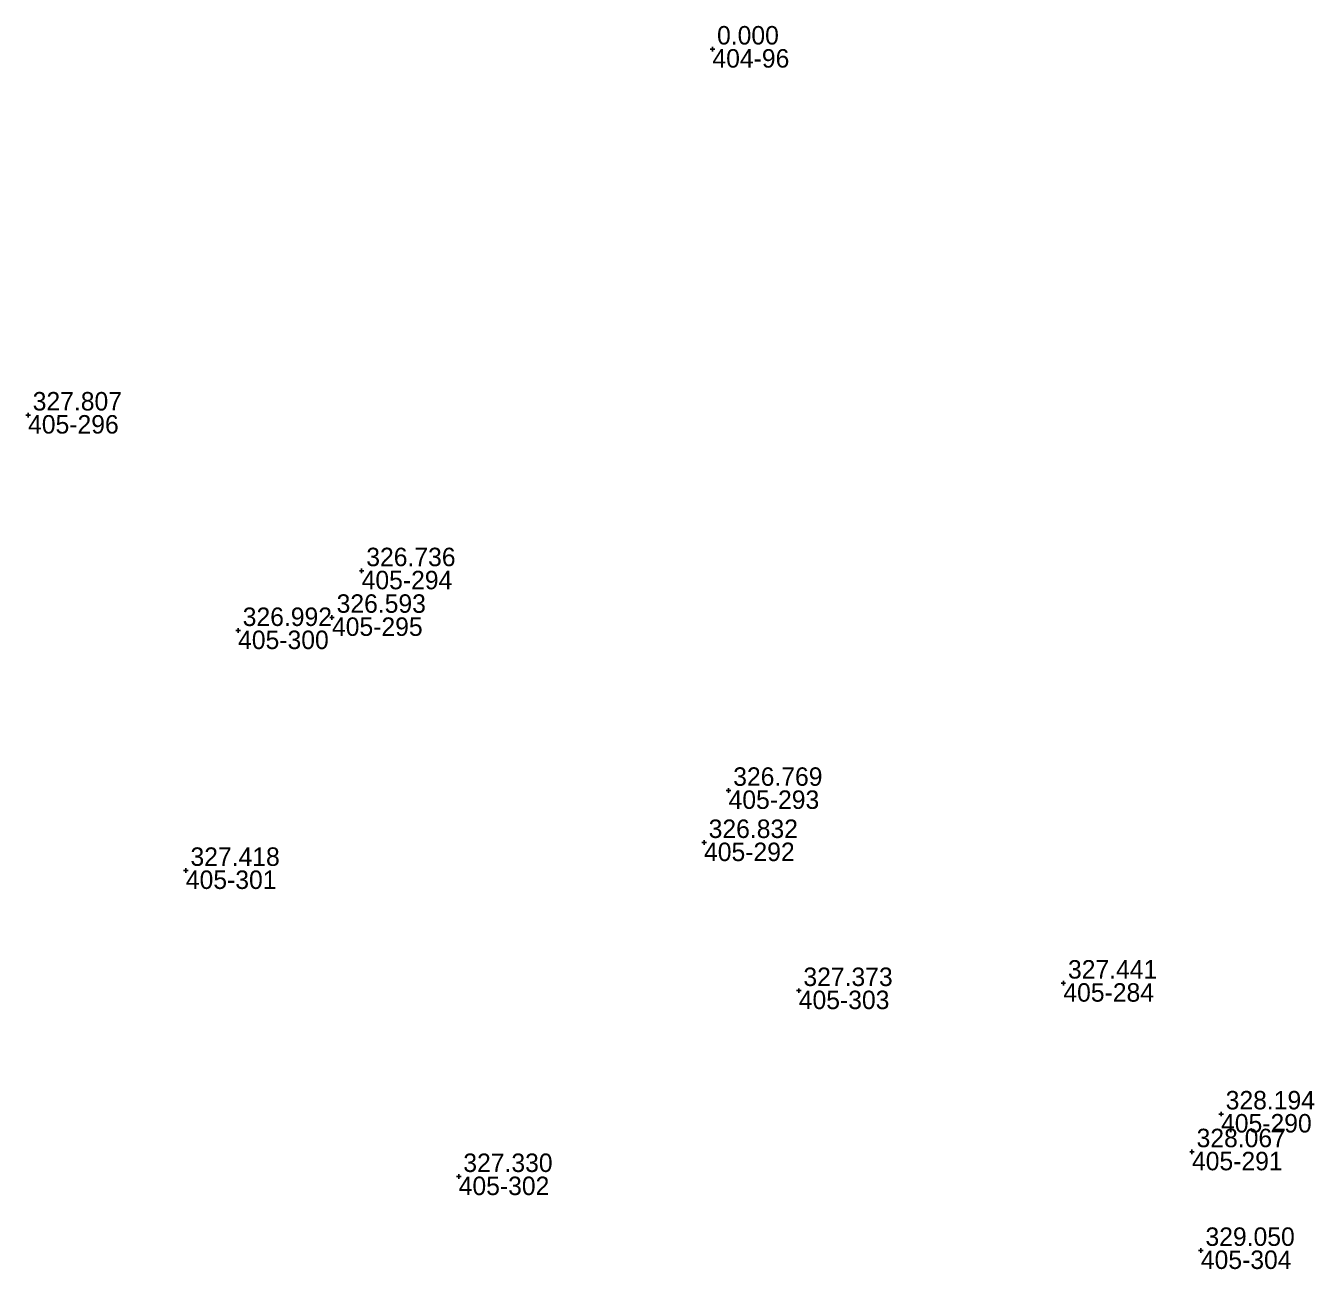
# Model space of a CAD drawing. Extents: x -829398 to -819400, y -1074439 to -1067977.
# Drawn here: x -826872.4 to -826788.7, y -1068786.5 to -1068705.7 of the extents above; entities that cross this region are included whole.
import ezdxf

# ---------------------------------------------------------------- set-up
doc = ezdxf.new("R2010")
doc.units = 0
for name, color, linetype in [('Vrstva 60', 7, 'Continuous'), ('Vrstva 61', 7, 'Continuous'), ('Čísla bodů_doměření_2012', 7, 'Continuous')]:
    doc.layers.add(name, color=color, linetype=linetype)

# ---------------------------------------------------------------- blocks, each defined once
blk = doc.blocks.new('BOD')
at = {"layer": 'Čísla bodů_doměření_2012'}
for p, q in [((-0.15, 0), (0.15, 0)), ((0, -0.15), (0, 0.15))]:
    blk.add_line(p, q, dxfattribs=at)

msp = doc.modelspace()

# ---------------------------------------------------------------- block references
at = {"layer": 'Vrstva 60'}
for p in [(-826827.8, -1068707.19), (-826872.263, -1068730.97), (-826850.59, -1068741.087), (-826852.517, -1068744.116), (-826858.618, -1068744.973), (-826826.75, -1068755.358), (-826828.345, -1068758.748), (-826862.012, -1068760.56), (-826822.19, -1068768.367), (-826805, -1068767.883), (-826794.754, -1068776.384), (-826796.643, -1068778.84), (-826844.285, -1068780.451), (-826796.066, -1068785.252)]:
    msp.add_blockref('BOD', p, dxfattribs=at)

# ---------------------------------------------------------------- texts
for s, p in [('404-96', (-826827.8, -1068708.39)), ('405-296', (-826872.263, -1068732.17)), ('405-294', (-826850.59, -1068742.287)), ('405-295', (-826852.517, -1068745.316)), ('405-300', (-826858.618, -1068746.173)), ('405-293', (-826826.75, -1068756.558)), ('405-292', (-826828.345, -1068759.948)), ('405-301', (-826862.012, -1068761.76)), ('405-284', (-826805, -1068769.083)), ('405-303', (-826822.19, -1068769.567)), ('405-290', (-826794.754, -1068777.584)), ('405-291', (-826796.643, -1068780.04)), ('405-302', (-826844.285, -1068781.651)), ('405-304', (-826796.066, -1068786.452))]:
    msp.add_text(s, height=1.2, dxfattribs=at).set_placement(p)
at = {"layer": 'Vrstva 61'}
for s, p in [('0.000', (-826827.5, -1068706.89)), ('327.807', (-826871.963, -1068730.67)), ('326.736', (-826850.29, -1068740.787)), ('326.593', (-826852.217, -1068743.816)), ('326.992', (-826858.318, -1068744.673)), ('326.769', (-826826.45, -1068755.058)), ('326.832', (-826828.045, -1068758.448)), ('327.418', (-826861.712, -1068760.26)), ('327.441', (-826804.7, -1068767.583)), ('327.373', (-826821.89, -1068768.067)), ('328.194', (-826794.454, -1068776.084)), ('328.067', (-826796.343, -1068778.54)), ('327.330', (-826843.985, -1068780.151)), ('329.050', (-826795.766, -1068784.952))]:
    msp.add_text(s, height=1.2, dxfattribs=at).set_placement(p)

doc.saveas('drawing.dxf')
